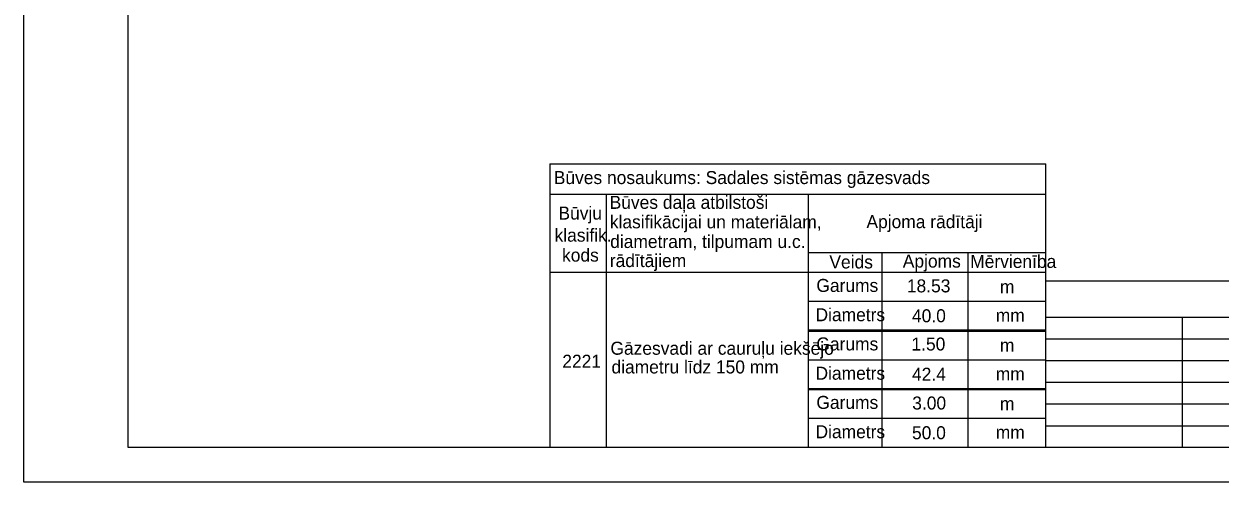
# Model space of a CAD drawing. Extents: x 515898 to 516108, y 302194 to 302343.
# Drawn here: x 515897.8 to 516035.7, y 302194.1 to 302247 of the extents above; entities that cross this region are included whole.
import ezdxf

# ---------------------------------------------------------------- set-up
doc = ezdxf.new("R2010")
doc.units = 0
doc.layers.add('RAMI_PLAN_####_TKST_#', color=7, linetype='Continuous')

msp = doc.modelspace()

# ---------------------------------------------------------------- linework, layer by layer
at = {"layer": 'RAMI_PLAN_####_TKST_#'}
for p, q in [((515958.4, 302230.87), (516015.59, 302230.87)), ((515958.4, 302230.87), (515958.4, 302198.13)), ((516015.59, 302198.13), (516015.59, 302230.87)), ((515958.4, 302227.38), (516015.59, 302227.38)), ((515964.9, 302227.38), (515964.9, 302198.13)), ((515988.2, 302227.38), (515988.2, 302198.13)), ((515988.2, 302220.63), (516015.59, 302220.63)), ((515996.68, 302220.63), (515996.68, 302198.13)), ((516006.59, 302220.63), (516006.59, 302198.13)), ((515958.4, 302218.38), (516015.59, 302218.38)), ((516015.59, 302217.37), (516103.78, 302217.37)), ((516015.59, 302198.13), (516015.59, 302217.37)), ((515988.2, 302215.01), (516015.59, 302215.01)), ((516015.59, 302213.18), (516063.53, 302213.18)), ((516031.32, 302198.13), (516031.32, 302213.18)), ((515988.2, 302211.7), (516015.59, 302211.7)), ((515988.2, 302211.67), (516015.59, 302211.67)), ((515988.2, 302211.63), (516015.59, 302211.63)), ((515988.2, 302211.6), (516015.59, 302211.6)), ((515988.2, 302211.56), (516015.59, 302211.56)), ((516015.59, 302210.68), (516063.53, 302210.68)), ((515988.2, 302208.26), (516015.59, 302208.26)), ((516015.59, 302208.17), (516063.53, 302208.17)), ((516015.59, 302205.66), (516063.53, 302205.66)), ((515988.2, 302204.95), (516015.59, 302204.95)), ((515988.2, 302204.92), (516015.59, 302204.92)), ((515988.2, 302204.88), (516015.59, 302204.88)), ((515988.2, 302204.85), (516015.59, 302204.85)), ((515988.2, 302204.81), (516015.59, 302204.81)), ((516015.59, 302203.15), (516103.78, 302203.15)), ((515988.2, 302201.51), (516015.59, 302201.51)), ((516015.59, 302200.64), (516103.78, 302200.64)), ((516103.78, 302198.13), (516006.48, 302198.13))]:
    msp.add_line(p, q, dxfattribs=at)
for points in [[(516107.78, 302194.13), (515897.78, 302194.13), (515897.78, 302342.63), (516107.78, 302342.63)], [(516103.78, 302198.13), (515909.78, 302198.13), (515909.78, 302338.63), (516103.78, 302338.63)]]:
    msp.add_lwpolyline(points, close=True, dxfattribs=at)

# ---------------------------------------------------------------- texts
for s, p in [('Būves nosaukums: Sadales sistēmas gāzesvads', (515958.86, 302228.53)), ('Būvju', (515959.4, 302224.43)), ('Būves daļa atbilstoši', (515965.3, 302225.67)), ('klasifikācijai un materiālam,', (515965.32, 302223.42)), ('Apjoma rādītāji', (515994.9, 302223.44)), ('klasifik.', (515958.95, 302221.88)), ('diametram, tilpumam u.c.', (515965.36, 302221.15)), ('kods', (515959.81, 302219.58)), ('rādītājiem', (515965.32, 302218.95)), ('Apjoms', (515999.09, 302218.89)), ('Mērvienība', (516006.86, 302218.85)), ('Veids', (515990.63, 302218.79)), ('Garums', (515989.13, 302216.08)), ('18.53', (515999.56, 302216.03)), ('m', (516010.29, 302215.93)), ('Diametrs', (515989.03, 302212.7)), ('40.0', (516000.15, 302212.58)), ('mm', (516009.81, 302212.63)), ('Garums', (515989.13, 302209.33)), ('1.50', (516000.09, 302209.32)), ('Gāzesvadi ar cauruļu iekšējo', (515965.39, 302208.83)), ('m', (516010.29, 302209.18)), ('2221', (515959.84, 302207.33)), ('diametru līdz 150 mm', (515965.51, 302206.67)), ('Diametrs', (515989.03, 302205.95)), ('42.4', (516000.15, 302205.83)), ('mm', (516009.81, 302205.88)), ('Garums', (515989.13, 302202.58)), ('3.00', (516000.18, 302202.51)), ('m', (516010.29, 302202.43)), ('Diametrs', (515989.03, 302199.2)), ('50.0', (516000.15, 302199.08)), ('mm', (516009.81, 302199.13))]:
    msp.add_text(s, height=1.5, dxfattribs=at).set_placement(p)

doc.saveas('drawing.dxf')
